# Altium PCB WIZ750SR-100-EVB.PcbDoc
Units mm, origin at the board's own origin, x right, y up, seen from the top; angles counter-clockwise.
Board outline 105 x 70 mm, 2 copper layers (Top Layer, Bottom Layer); 94 components, 77 nets, 337 pads, 84 vias.
Unrouted connection lines stored in the file: 2.
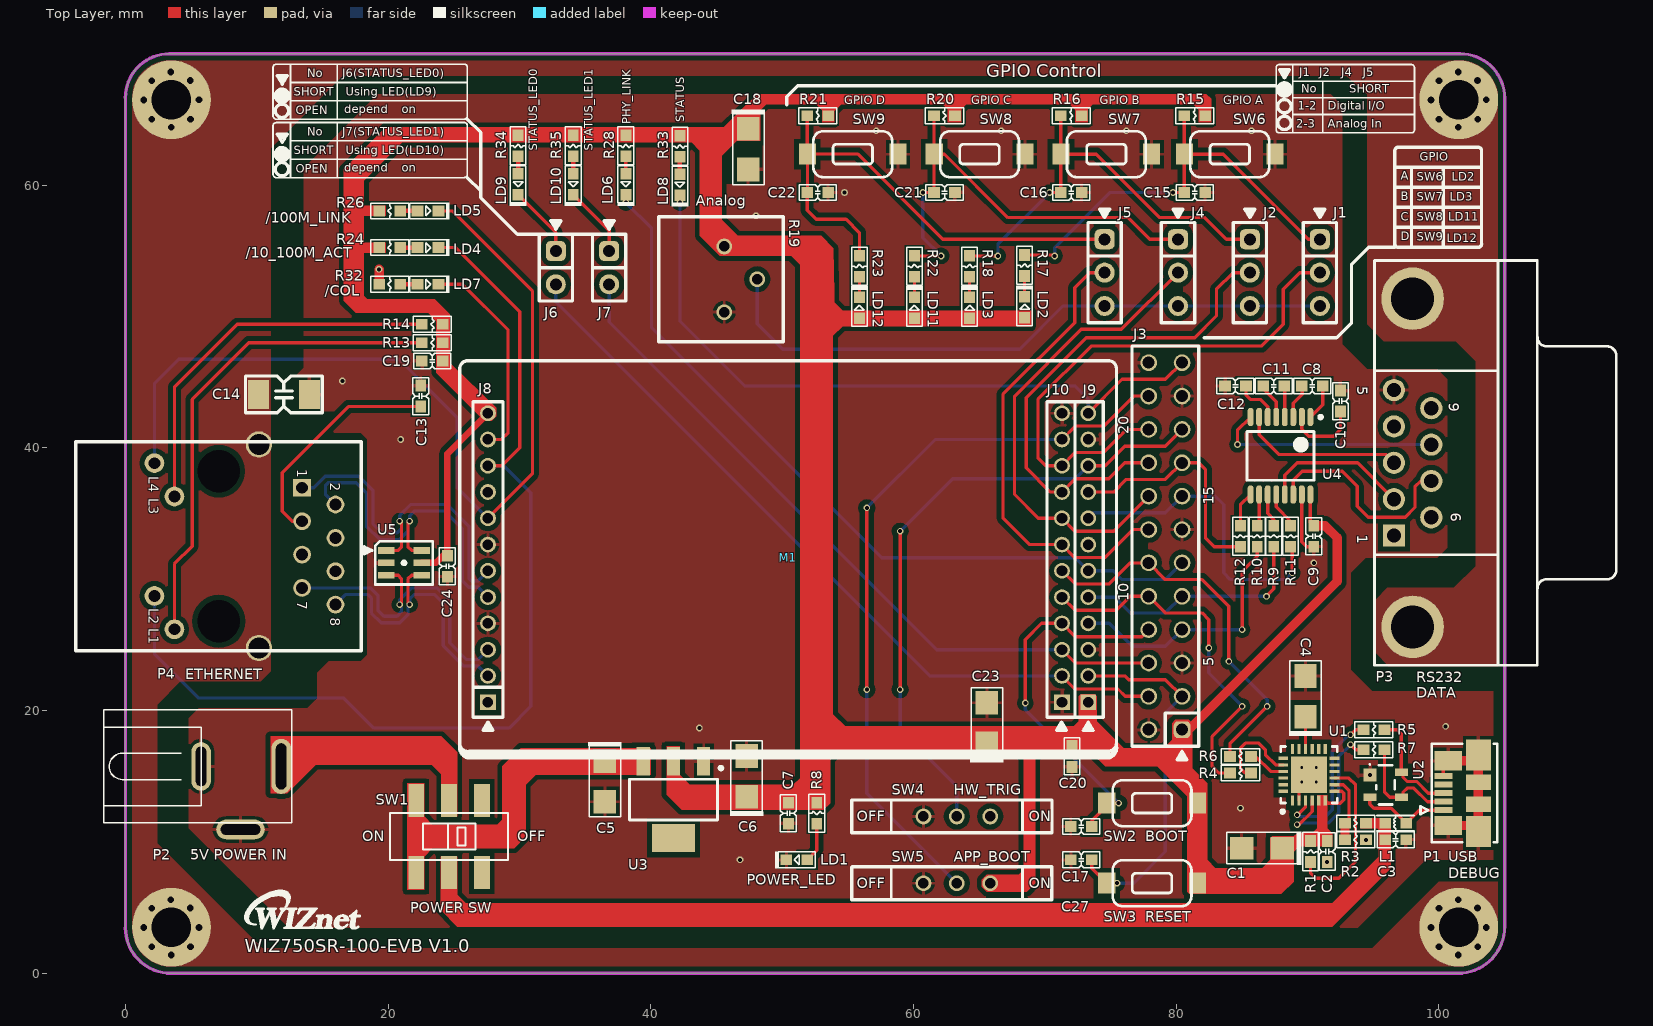
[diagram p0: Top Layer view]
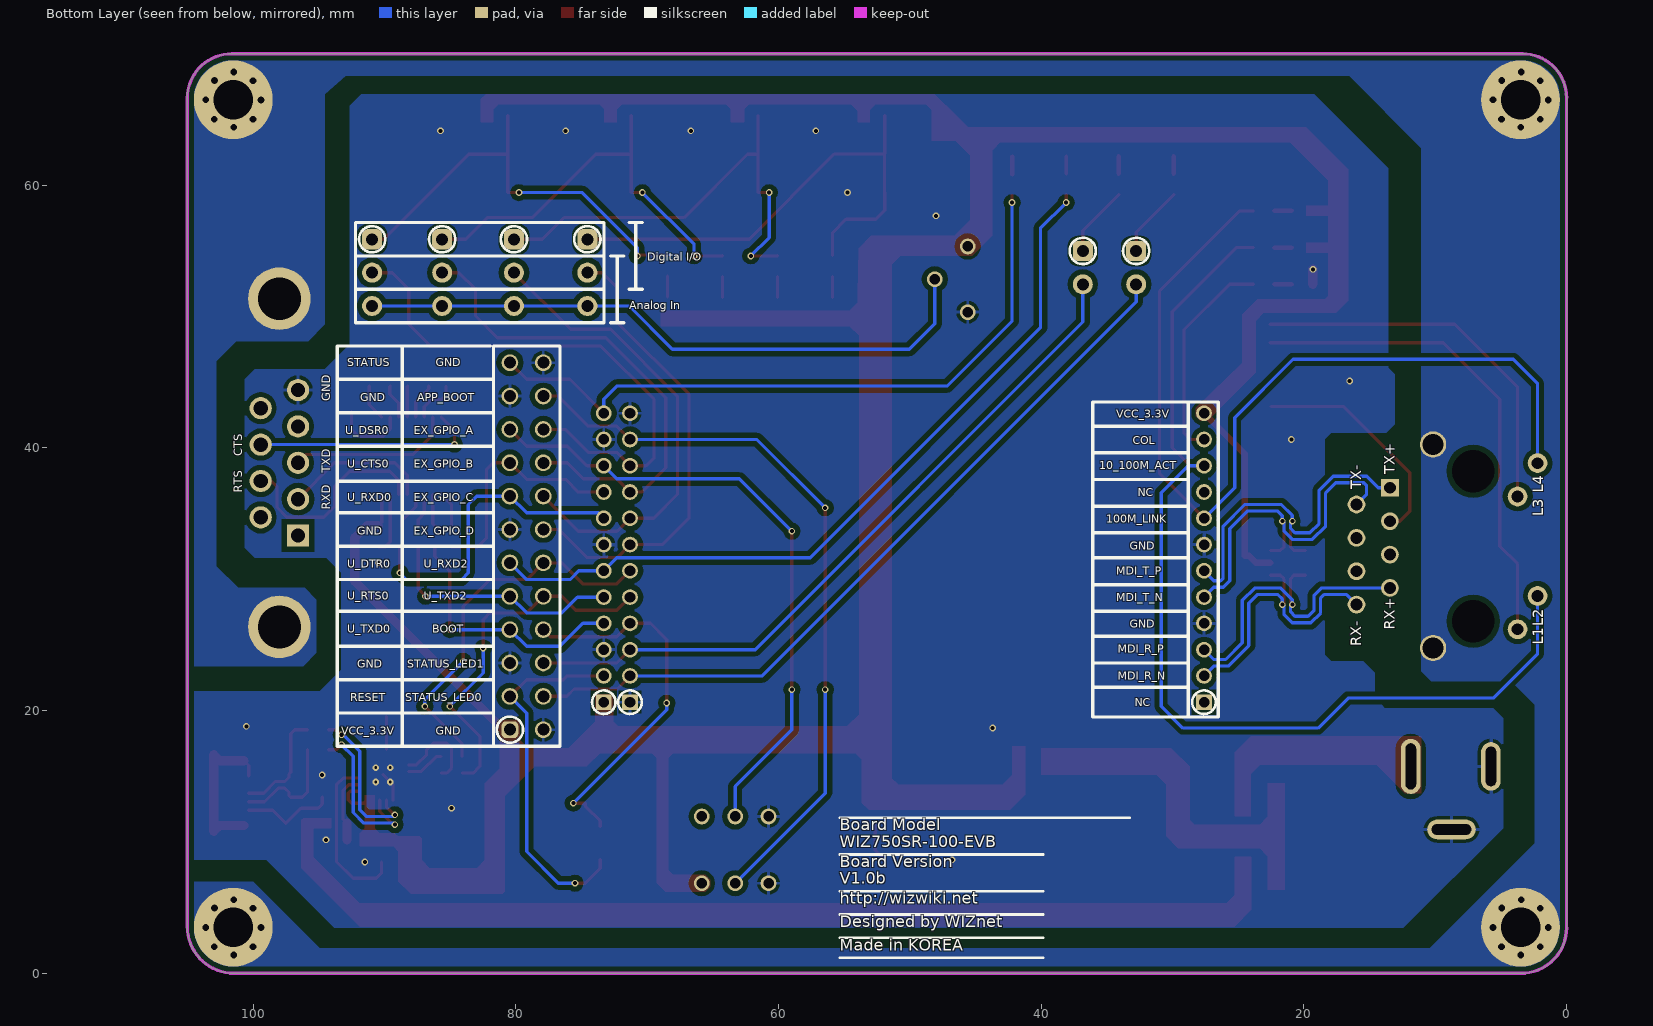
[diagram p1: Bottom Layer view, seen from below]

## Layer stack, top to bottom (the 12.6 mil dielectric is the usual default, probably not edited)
Top Solder: solder mask 0.0102, Solder Resist, Dk 3.5
Top Layer: signal copper 0.0356
Dielectric 1: dielectric 0.32, FR-4, Dk 4.8
Bottom Layer: signal copper 0.0356
Bottom Solder: solder mask 0.0102, Solder Resist, Dk 3.5

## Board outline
0,3.458 ccw(c3.458,3.458) 3.458,0 101.448,0 ccw(c101.448,3.555) 105.004,3.555 105.004,66.625 ccw(c101.629,66.625) 101.629,70 3.347,70 ccw(c3.347,66.653) 0,66.653 0.004,66.653

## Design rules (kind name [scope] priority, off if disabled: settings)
Clearance [All] p1: gap=0.15 except(0.381: Arc-Poly Track-Poly SMDPad-Poly THPad-Poly Via-Poly Fill-Poly Poly-Poly Poly-Region)
DiffPairsRouting [All] p1: maxlimit=0.25 minlimit=0.25 mostfreqgap=0.25 toplayer_minwidth=0.25 toplayer_maxwidth=0.25 toplayer_prefwidth=0.25 bottomlayer_minwidth=0.25 bottomlayer_maxwidth=0.25 bottomlayer_prefwidth=0.25 maxuncoupledlength=12.7
PolygonConnect PolygonConnect_2 [IsPad vs IsNamedPolygon('TOP-GND')Or IsNamedPolygon('BOTTOM-GND')] p1: connectstyle=Relief reliefconductorwidth=0.254 reliefentries=4 polygonreliefangle="90 Angle" airgapwidth=0.254
PolygonConnect PolygonConnect_1 [IsVia] p2: connectstyle=Direct reliefconductorwidth=0.254 reliefentries=4 polygonreliefangle="90 Angle" airgapwidth=0.254
PolygonConnect [All] p3: connectstyle=Direct reliefconductorwidth=0.254 reliefentries=4 polygonreliefangle="90 Angle" airgapwidth=0.254
RoutingVias [All] p1: holewidth=0.305 width=0.508 viastyle="Through Hole" minholewidth=0.305 minwidth=0.508 maxholewidth=0.508 maxwidth=0.762
SolderMaskExpansion [All] p1: expansion=0.102
Width [All] p1: maxlimit=0.705 minlimit=0.25 preferedwidth=0.25 minimp=50.000000 maximp=50.000000 favimp=50.000000
29 further rules are at their usual default settings.

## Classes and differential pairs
differential pair D: +D_P -D_N
differential pair MDI_R: +MDI_R_P -MDI_R_N
differential pair MDI_T: +MDI_T_P -MDI_T_N
differential pair USB_D: +USB_D_P -USB_D_N

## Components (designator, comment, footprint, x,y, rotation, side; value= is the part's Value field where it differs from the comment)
C1 "4.7uF/16V" "CAP-A Size" 86.529,9.525 r180 top
C2 "0.1uF" CAP-0603 91.491,9.271 r90 top
C3 "0.1uF" CAP-0603 96.698,10.16 r180 top
C4 "4.7uF/16V" "CAP-A Size" 89.84,21.082 r90 top
C5 "10uF/16V" "CAP-A Size" 36.5,14.605 r270 top
C6 "10uF/16V" "CAP-A Size" 47.295,14.986 r90 top
C7 "0.1uF" CAP-0603 50.47,12.192 r90 top
C8 "0.1uF" CAP-0603 90.348,44.704 r180 top
C9 "0.1uF" CAP-0603 90.475,33.274 r90 top
C10 "0.1uF" CAP-0603 92.507,43.561 r270 top
C11 "0.1uF" CAP-0603 87.427,44.704 r180 top
C12 "0.1uF" CAP-0603 84.506,44.704 r0 top
C13 "0.1uF" CAP-0603 22.479,43.942 r270 top
C14 "1nF/2kV" CAP-1808 12.065,44.069 r180 top
C15 "0.1uF" CAP-0603 81.407,59.436 r180 top
C16 "0.1uF" CAP-0603 72.009,59.436 r180 top
C17 "0.1uF" CAP-0603 72.771,11.176 r0 top
C18 "4.7uF/16V" "CAP-A Size" 47.422,62.738 r270 top
C19 "0.1uF" CAP-0603 23.368,46.609 r0 top
C20 "0.1uF" CAP-0603 72.06,16.51 r90 top
C21 "0.1uF" CAP-0603 62.357,59.436 r180 top
C22 "0.1uF" CAP-0603 52.705,59.436 r180 top
C23 "4.7uF/16V" "CAP-A Size" 65.583,19.05 r90 top
C24 "0.1uF" CAP-0603 24.511,30.988 r270 top
C27 "0.1uF" CAP-0603 72.771,8.636 r0 top
J1 "2.54mm 1x3 Pin Header DIP" IDC-1X3 90.932,55.88 r270 top
J2 "2.54mm 1x3 Pin Header DIP" IDC-1X3 85.598,55.88 r270 top
J3 "2.54mm 2x12 Pin" IDC-2x12_socket_2.54mm 80.442,18.542 r90 top
J4 "2.54mm 1x3 Pin Header DIP" IDC-1X3 80.137,55.88 r270 top
J5 "2.54mm 1x3 Pin Header DIP" IDC-1X3 74.549,55.88 r270 top
J6 "2.54mm 1x2 Pin Header DIP" IDC-1X2 32.766,54.991 r270 top
J7 "2.54mm 1x2 Pin Header DIP" IDC-1X2 36.83,54.991 r270 top
L1 "HH-1M1608-121JT" IND-0603 96.698,11.43 r180 top
LD1 "RED-0603" LED-0603-RED 51.105,8.636 r180 top
LD2 "GREEN-0603" LED-0603-GREEN 68.453,50.711 r90 top
LD3 "GREEN-0603" LED-0603-GREEN 64.262,50.66 r90 top
LD4 "GREEN-0603" LED-0603-GREEN 23.038,55.245 r0 top
LD5 "YELLOW-0603" LED-0603-YELLOW 23.038,58.039 r0 top
LD6 "BLUE-0603" LED-0603-GREEN 38.1,60.071 r270 top
LD7 "GREEN-0603" LED-0603-GREEN 23.038,52.451 r0 top
LD8 "GREEN-0603" LED-0603-GREEN 42.215,60.033 r270 top
LD9 "GREEN-0603" LED-0603-GREEN 29.896,60.071 r270 top
LD10 "GREEN-0603" LED-0603-GREEN 34.087,60.071 r270 top
LD11 "GREEN-0603" LED-0603-GREEN 60.071,50.66 r90 top
LD12 "GREEN-0603" LED-0603-GREEN 55.88,50.66 r90 top
M1 "WIZ750SR-100_V1.0" WIZ750JR_V1.0 25.451,16.637 r0 top
P1 "47346-0001" USB-MICRO-B(SMD) 104.445,13.716 r180 top
P2 "DC-JACK 2pi" "DC-JACK 2pi" 8.763,15.748 r270 top
P3 "D-SUB9-MALE" D-SUB9-MALE 107.493,38.862 r270 top
P4 "BS-RB10005" RJ45-125BAG1A 7.112,32.512 r270 top
R1 "4.7K" RES-0603 90.221,9.271 r90 top
R2 "47K" RES-0603 93.65,10.16 r180 top
R3 "24K" RES-0603 93.65,11.43 r0 top
R4 "0R" RES-0603 84.887,15.24 r180 top
R5 "22R" RES-0603 95.047,17.018 r180 top
R6 "0R" RES-0603 84.887,16.51 r180 top
R7 "22R" RES-0603 95.047,18.542 r180 top
R8 "330R" RES-0603 52.629,12.192 r270 top
R9 "0R" RES-0603 87.427,33.274 r90 top
R10 "0R" RES-0603 86.157,33.274 r90 top
R11 "0R" RES-0603 88.697,33.274 r90 top
R12 "0R" RES-0603 84.887,33.274 r90 top
R13 "330R" RES-0603 23.368,48.006 r180 top
R14 "330R" RES-0603 23.368,49.403 r180 top
R15 "4.7K" RES-0603 81.407,65.278 r0 top
R16 "4.7K" RES-0603 72.009,65.278 r0 top
R17 "330R" RES-0603 68.453,53.886 r90 top
R18 "330R" RES-0603 64.262,53.835 r90 top
R19 "WIW3386P" WIW3386P 45.593,52.832 r90 top
R20 "4.7K" RES-0603 62.357,65.278 r0 top
R21 "4.7K" RES-0603 52.705,65.278 r0 top
R22 "330R" RES-0603 60.071,53.835 r90 top
R23 "330R" RES-0603 55.88,53.835 r90 top
R24 "330R" RES-0603 20.117,55.245 r180 top
R26 "330R" RES-0603 20.117,58.039 r180 top
R28 "1K" RES-0603 38.1,62.992 r90 top
R32 "330R" RES-0603 20.117,52.451 r180 top
R33 "330R" RES-0603 42.215,62.954 r90 top
R34 "330R" RES-0603 29.896,62.992 r90 top
R35 "330R" RES-0603 34.087,62.992 r90 top
SW1 "Switch" JS202011SCQN 24.638,10.414 r0 top
SW2 "ITS-1107(SMD)" ITS-1107(SMD) 78.156,12.954 r0 top
SW3 "ITS-1107(SMD)" ITS-1107(SMD) 78.156,6.858 r0 top
SW4 "ITS-12H" ITS-12H 63.297,11.938 r180 top
SW5 "ITS-12H" ITS-12H 63.297,6.858 r180 top
SW6 "ITS-1107(SMD)" ITS-1107(SMD) 84.074,62.357 r180 top
SW7 "ITS-1107(SMD)" ITS-1107(SMD) 74.676,62.357 r180 top
SW8 "ITS-1107(SMD)" ITS-1107(SMD) 65.024,62.357 r180 top
SW9 "ITS-1107(SMD)" ITS-1107(SMD) 55.372,62.357 r180 top
U1 "CP2104-GM" CP2104_QFN24_PAD 90.094,15.113 r90 top
U2 "SP0503BAHTG" SP0503BAHTG 95.936,14.351 r0 top
U3 "IL1117C-33ET" IL1117C-33ET 41.723,13.218 r270 top
U4 "SP3232EBEY" SP3232EBEY-TSSOP16 87.935,39.395 r270 top
U5 "TPD4S009" SOT-23-6L 21.209,31.242 r0 top

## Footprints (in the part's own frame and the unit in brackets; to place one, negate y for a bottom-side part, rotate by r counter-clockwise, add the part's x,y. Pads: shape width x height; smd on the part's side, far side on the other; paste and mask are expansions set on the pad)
CAP-0603 [mm] "Ceramic CAP 0603(1608)"
  rect 0.89x0.82 smd: 1(-0.8,0) 2(0.8,0)
  silkscreen extent -1.41,-0.6 1.41,0.6, body extent -0.93,-0.41 0.93,0.41, height 0.81
CAP-1808 [mm] "Ceramic CAP 1808(4520)"
  rect 1.6x2.2 smd: 1(-1.95,0) 2(1.95,0)
  silkscreen extent -2.92,-1.4 2.92,1.4, body extent -2.25,-1.02 2.25,1.01, height 2
"CAP-A Size" [mm] "Tantal CAP A Size EIA/IECQ 3216"
  rect 1.8x1.7 smd: 1(-1.55,0) 2(1.55,0)
  silkscreen extent -3,-1.25 2.7,1.25, body extent -1.67,-0.78 1.72,0.82, height 1.75
CP2104_QFN24_PAD [mm] "QFN, 24-Leads, Body 4.00x4.00mm, Pitch 0.50mm, Thermal Pad 2.75x2.75mm, IPC Medium Density"
  rect 0.75x0.25 smd: 1(-1.95,1.25) 2(-1.95,0.75) 3(-1.95,0.25) 4(-1.95,-0.25) 5(-1.95,-0.75) 6(-1.95,-1.25) 13(1.95,-1.25) 14(1.95,-0.75) 15(1.95,-0.25) 16(1.95,0.25) 17(1.95,0.75) 18(1.95,1.25)
  rect 0.25x0.75 smd: 7(-1.25,-1.95) 8(-0.75,-1.95) 9(-0.25,-1.95) 10(0.25,-1.95) 11(0.75,-1.95) 12(1.25,-1.95) 19(1.25,1.95) 20(0.75,1.95) 21(0.25,1.95) 22(-0.25,1.95) 23(-0.75,1.95) 24(-1.25,1.95)
  rect 2.75x2.75 smd: 25(0,0)
  silkscreen extent -2.92,-2.15 2.15,2.15, body extent -2,-2 2,2, height 0.8
D-SUB9-MALE [mm] "D-SUB9, MALE, Right Angle;"
  rect 1.69x1.69 hole 1.09: 1(5.54,-10.92)
  round 1.69 hole 1.09: 2(2.77,-10.92) 3(0,-10.92) 4(-2.77,-10.92) 5(-5.54,-10.92) 6(4.155,-8.08) 7(1.385,-8.08) 8(-1.385,-8.08) 9(-4.155,-8.08)
  round 4.76 hole 3.26: 10(-12.495,-9.5) 11(12.495,-9.5)
  silkscreen extent -15.4,-12.4 15.4,6, body extent -15.38,-12.55 15.43,6.05, height 12.57
"DC-JACK 2pi" [mm] "DC-JACK 2pi"
  oval 4.2x1.5 hole 0.8 slot 3.5 at 0 deg: 1(0,3.1)
  oval 1.5x3.7 hole 0.8 slot 3 at 90 deg: 2(4.8,0)
  oval 3.7x1.5 hole 0.8 slot 3 at 0 deg: 3(0,-3)
  silkscreen extent -4.3,-10.4 4.3,3.9, body extent -4.42,-10.49 5.05,3.99, height 11.18
IDC-1X2 [mil]
  rrect50% 60x60 hole 36: 1(0,0)
  round 60 hole 36: 2(100,0)
  silkscreen extent -90,-50 150,50, body extent -49,-49 151,51, height 336
IDC-1X3 [mil]
  rrect50% 60x60 hole 36: 1(0,0)
  round 60 hole 36: 2(100,0) 3(200,0)
  silkscreen extent -90,-50 250,50, body extent -46,-49 254,49, height 323
IDC-2x12_socket_2.54mm [mil] "IDC-2x12_HEADER"
  rrect50% 50x50 hole 36: 1(0,0)
  round 50 hole 36: 2(0,100) 3(100,0) 4(100,100) 5(200,0) 6(200,100) 7(300,0) 8(300,100) 9(400,0) 10(400,100) 11(500,0) 12(500,100) 13(600,0) 14(600,100) 15(700,0) 16(700,100) 17(800,0) 18(800,100) 19(900,0) 20(900,100) 21(1000,0) 22(1000,100) 23(1100,0) 24(1100,100)
  silkscreen extent -90,-50 1150,150, body extent -60,-45 1160,155, height 325
IL1117C-33ET [mm] "SOT223, 4-Leads, Body 6.45x7.80mm (avg), Pitch 2.30mm, IPC Medium Density"
  rect 2.15x1 smd: 1(-2.925,2.3) 2(-2.925,0) 3(-2.925,-2.3)
  rect 2.15x3.25 smd: 4(2.925,0)
  silkscreen extent -2.53,-3.35 1.55,3.74, body extent -3.54,-3.25 3.54,3.25, height 1.65
IND-0603 [mm]
  rect 0.89x0.82 smd: 1(-0.8,0) 2(0.8,0)
  silkscreen extent -1.4,-0.6 1.4,0.6, body extent -0.8,-0.4 0.8,0.4, height 0.95
ITS-12H [mm] "Silde Switch"
  round 1.2 hole 0.8: 1(0,0) 2(-2.54,0) 3(2.54,0)
  silkscreen extent -5,-1.25 5,1.25, body extent -5,-1.22 5,1.22, height 6.4
ITS-1107(SMD) [mm] "TACT SW, SMD"
  rect 1.3x1.6 smd: 1(-3.45,0) 2(3.45,0)
  silkscreen extent -3,-1.75 3,1.75, body extent -3.05,-1.85 3.05,1.85, height 2.5
JS202011SCQN [mm]
  rect 1.2x2.5 smd: 1(-2.5,-2.75) 2(0,-2.75) 3(2.5,-2.75) 4(-2.5,2.75) 5(0,2.75) 6(2.5,2.75)
  silkscreen extent -4.5,-1.8 4.5,1.8, body extent -4.52,-3.75 4.52,3.75, height 5.5
LED-0603-GREEN [mm]
  rect 0.89x0.82 smd: 1(-0.8,0) 2(0.8,0)
  silkscreen extent -1.41,-0.65 1.65,0.65, body extent -0.85,-0.45 0.85,0.45, height 0.9
LED-0603-RED [mm]
  rect 0.89x0.82 smd: 1(-0.8,0) 2(0.8,0)
  silkscreen extent -1.41,-0.65 1.65,0.65, body extent -0.85,-0.45 0.85,0.45, height 0.9
LED-0603-YELLOW [mm]
  rect 0.89x0.82 smd: 1(-0.8,0) 2(0.8,0)
  silkscreen extent -1.41,-0.65 1.65,0.65, body extent -0.8,-0.4 0.8,0.4, height 0.6
RES-0603 [mm] "RES-0603"
  rect 0.89x0.82 smd: 1(-0.8,0) 2(0.8,0)
  silkscreen extent -1.45,-0.6 1.45,0.6, body extent -0.82,-0.41 0.82,0.41, height 0.46
RJ45-125BAG1A [mm]
  round 1.5 hole 0.89: L1(6.325,-3.38) L2(3.785,-4.9) L3(-3.785,-3.38) L4(-6.325,-4.9)
  rect 1.35x1.35 hole 0.9: R1(-4.445,6.34)
  round 1.35 hole 0.9: R2(-3.175,8.88) R3(-1.905,6.34) R4(-0.635,8.88) R5(0.635,6.34) R6(1.905,8.88) R7(3.175,6.34) R8(4.445,8.88)
  round 2 hole 1.6: R9(-7.75,3.05) R10(7.75,3.05)
  round 1.8 hole 3.25: ""(-5.715,0) ""(5.715,0)
  silkscreen extent -7.95,-10.89 7.95,10.83, body extent -8.03,-10.8 7.97,10.5, height 13.1
SOT-23-6L [mm]
  rect 1.27x0.508 smd: 1(-1.34,0.95) 2(-1.34,0) 3(-1.34,-0.95) 4(1.34,-0.95) 5(1.34,0) 6(1.34,0.95)
  silkscreen extent -3.02,-1.65 2.2,1.65, body extent -1.21,-1.4 1.21,1.4, height 1.09
SP0503BAHTG [mm] "SOT143, 4-Leads, Body 2.92x2.37mm, Pitch 1.90mm, IPC Medium Density"
  rect 1x1 smd: 1(-1.2,0.75)
  rect 1x0.6 smd: 2(-1.2,-0.95) 3(1.2,-0.95) 4(1.2,0.95)
  silkscreen extent -1.25,-1.5 0.7,1.6, body extent -0.7,-1.52 0.7,1.52, height 1.22
SP3232EBEY-TSSOP16 [mm] "True +3.0V to +5.5V RS-232 Transceivers"
  oval 1.4x0.45 smd: 1(-2.95,2.275) 2(-2.95,1.625) 3(-2.95,0.975) 4(-2.95,0.325) 5(-2.95,-0.325) 6(-2.95,-0.975) 7(-2.95,-1.625) 8(-2.95,-2.275) 9(2.95,-2.275) 10(2.95,-1.625) 11(2.95,-0.975) 12(2.95,-0.325) 13(2.95,0.325) 14(2.95,0.975) 15(2.95,1.625) 16(2.95,2.275)
  silkscreen extent -3.07,-2.55 1.85,3.17, body extent -3.16,-2.49 3.12,2.51, height 1.09
USB-MICRO-B(SMD) [mm] "MOLEX SD-47346-001"
  rect 1.38x0.45 smd: 1(4.11,1.3) 2(4.11,0.65) 3(4.11,0) 4(4.11,-0.65) 5(4.11,-1.3)
  rect 2.1x1.475 smd: 6(3.75,2.462) 7(3.75,-2.462)
  rect 1.9x2.375 smd: 8(1.45,2.913) 11(1.45,-2.913)
  rect 1.9x1.175 smd: 9(1.45,0.837) 10(1.45,-0.837)
  silkscreen extent 0,-3.75 5.85,3.75, body extent -0.43,-4.1 5,4.1, height 2.98
WIW3386P [mm] "Potentiometer 10KR, Hongxing, 8mm shaft"
  round 1.2 hole 0.8: 1(2.5,0) 2(0,-2.5) 3(-2.5,0)
  silkscreen extent -4.75,-4.5 4.75,5, body extent -3.3,-3.3 3.3,3.75, height 4.7
WIZ750JR_V1.0 [mm] "WIZ750JR_V1.0, Serial to Ethernet Module, W7500P"
  rect 1.2x1.2 hole 0.8: J1-1(47.85,4) J2-1(2.15,4) J3-1(45.85,4)
  round 1.2 hole 0.8: J1-2(47.85,6) J1-3(47.85,8) J1-4(47.85,10) J1-5(47.85,12) J1-6(47.85,14) J1-7(47.85,16) J1-8(47.85,18) J1-9(47.85,20) J1-10(47.85,22) J1-11(47.85,24) J1-12(47.85,26) J2-2(2.15,6) J2-3(2.15,8) J2-4(2.15,10) J2-5(2.15,12) J2-6(2.15,14) J2-7(2.15,16) J2-8(2.15,18) J2-9(2.15,20) J2-10(2.15,22) J2-11(2.15,24) J2-12(2.15,26) J3-2(45.85,6) J3-3(45.85,8) J3-4(45.85,10) J3-5(45.85,12) J3-6(45.85,14) J3-7(45.85,16) J3-8(45.85,18) J3-9(45.85,20) J3-10(45.85,22) J3-11(45.85,24) J3-12(45.85,26)
  silkscreen extent 0,0 50,30, body extent 1.13,2.79 48.75,26.79, height 6

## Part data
C1 C4 C5 C6 C18 C23: library part "CAP-A Size", "Tantla CAP A Size EIA/IECQ 3216"
C2 C3 C7 C8 C9 C10 C11 C12 C13 C15 C16 C17 C19 C20 C21 C22 C24 C27: library part CAP-0603, "Ceramic CAP 0603(1608)"
C14: library part CAP-1808, "Ceramic CAP 1808(4520)"
J3: library part "Header 2x12", "pin header 2.54mm 2x12"
J6 J7: library part "Header 1x2", "pin header 2.54mm 1x2"
L1: library part IND-0603, "Inductor 0603(1608)"
LD1 LD2 LD3 LD4 LD5 LD6 LD7 LD8 LD9 LD10 LD11 LD12: library part LED-0603, "LED-0603"
M1: library part WIZ750JR_V0.2, "Serial to ethernet module, 50mmx30mm, 7500 + External PHY"
P1: "MICRO USB B Type"
P3: "D-SUB-9, MALE,  Right Angle"
P4: library part RB1-125BAG1A, "10/100 BASE-TX MAGJACK"
R1 R2 R3 R4 R5 R6 R7 R8 R9 R10 R11 R12 R13 R14 R15 R16 R17 R18 R20 R21 R22 R23 R24 R26 R28 R32 R33 R34 R35: library part RES-0603, "RES-0603"
R19: "Potentiometer"
SW1: "SMD slide Switch (ON-ON)"
SW2 SW3 SW6 SW7 SW8 SW9: "TACT SW, SMD"
SW4 SW5: "Slide Switch"
U1: "USB to UART Bridge, SiliconLabs"
U2: "Little Fuse, Silicon Protection Array Products"
U3: "1A, 3.3V"
U4: "True +3.0V to +5.5V RS-232 Transceivers TSSOP16"
U5: library part tpd4s009, "6-PIN SOT DBVor DCK Package"

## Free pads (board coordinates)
  round 6 hole 3: ""(3.5,3.5) ""(3.5,66.5) ""(101.5,3.5) ""(101.5,66.5)

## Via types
v1: diameter 0.508, hole 0.305, Top Layer to Bottom Layer, tented both sides, 48 vias
v2: diameter 0.762, hole 0.508, Top Layer to Bottom Layer, tented both sides, 32 vias
v3: diameter 0.5, hole 0.2, Top Layer to Bottom Layer, 4 vias

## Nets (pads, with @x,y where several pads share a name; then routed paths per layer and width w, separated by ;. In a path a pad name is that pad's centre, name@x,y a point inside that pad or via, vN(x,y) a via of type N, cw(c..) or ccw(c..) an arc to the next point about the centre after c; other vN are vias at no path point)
5V: C5.1 SW1.1 SW1.4 U3.3
100M_LINK_LED: LD5.2 M1.J2-8 P4.L4 | length 68.7
  Top Layer w0.25: LD5.2 24.892,58.039 30.988,51.943 30.988,38.024 M1.J2-8
  Bottom Layer w0.25: P4.L4 2.212,44.884 4.064,46.736 20.828,46.736 25.273,42.291 25.273,36.965 M1.J2-8
ACT_LED: LD4.2 M1.J2-10 P4.L2 | length 78
  Top Layer w0.25: LD4.2 25.146,55.245 30.023,50.368 30.023,40.005 28.655,38.637 M1.J2-10
  Bottom Layer w0.25: P4.L2 2.212,24.331 5.588,20.955 16.637,20.955 18.923,18.669 29.21,18.669 30.861,20.32 30.861,36.576 28.8,38.637 M1.J2-10
ADC0: J1.3 J2.3 J4.3 J5.3 R19.2 | length 48.4
  Bottom Layer w0.25: R19.2 48.093,49.443 50.038,47.498 68.072,47.498 71.374,50.8 J5.3 J4.3 J2.3 J1.3
APP_BOOT: J3.22 M1.J3-11 SW5.1 | length 56.4
  Top Layer w0.25: v1(56.439,21.59) v1(56.439,35.433) ; M1.J3-11 72.32,41.656 74.473,41.656 76.759,43.942 J3.22
  Bottom Layer w0.25: v1(56.439,21.59) 56.439,13.716 SW5.1 ; v1(56.439,35.433) 61.643,40.637 M1.J3-11
BOOT: C17.2 J3.8 M1.J3-4 SW2.1 | length 29.1
  Top Layer w0.25: v1(68.504,20.574) 68.504,25.4 69.741,26.637 M1.J3-4 72.309,25.629 77.368,25.629 J3.8 ; C17.2 73.571,11.595 74.706,12.73 SW2.1 v1(75.616,12.954)
  Bottom Layer w0.25: v1(68.504,20.574) 68.504,20.066 v1(75.616,12.954)
CH_GND: C14.2 P3.10 P3.11 P4.R9 P4.R10 pad.
  other v2: 3.478,1.398 101.478,1.398 2.005,2.008 4.951,2.008 100.005,2.008 102.951,2.008 1.395,3.481 5.598,3.49 99.395,3.481 103.598,3.49 2.005,4.954 4.938,4.963 100.005,4.954 102.938,4.963 3.46,5.609 101.46,5.609 3.478,64.398 101.478,64.398 2.005,65.008 4.951,65.008 100.005,65.008 102.951,65.008 1.395,66.481 99.395,66.481 5.598,66.49 103.598,66.49 2.005,67.954 100.005,67.954 4.938,67.963 102.938,67.963 3.46,68.609 101.46,68.609
COL_LED: LD7.2 M1.J2-11 | length 16.3
  Top Layer w0.25: LD7.2 25.654,52.451 29.134,48.971 29.134,41.148 28.623,40.637 M1.J2-11
D_N: P1.2 R5.1 U2.3 | length 8.7
  Top Layer w0.25: R5.1 95.847,13.805 96.251,13.401 U2.3 97.261,13.526 97.261,13.775 97.587,14.101 98.091,14.101 99.126,13.066 P1.2
D_P: P1.3 R7.1 U2.4 | length 8.3
  Top Layer w0.25: R7.1 96.825,18.542 97.136,18.231 U2.4 97.261,15.176 97.261,14.927 97.587,14.601 98.298,14.601 99.183,13.716 P1.3
DB_CTS: P3.8 U4.8 | length 17.3
  Top Layer w0.25: v1(84.657,40.259) 84.657,41.342 U4.8
  Bottom Layer w0.25: v1(84.657,40.259) 84.645,40.247 P3.8
DB_RTS: P3.7 U4.14 | length 16.3
  Top Layer w0.25: U4.14 88.91,37.551 89.586,38.227 92.634,38.227 93.777,37.084 93.777,35.56 94.615,34.722 97.434,34.722 98.171,35.458 98.171,37.033 98.615,37.477 P3.7
DB_RXD: P3.2 U4.13 | length 11.3
  Top Layer w0.25: U4.13 88.26,37.917 89.205,38.862 93.803,38.862 P3.2
DB_TXD: P3.3 U4.7 | length 12.5
  Top Layer w0.25: U4.7 86.31,40.995 87.808,39.497 95.938,39.497 P3.3
EX_GPIO_A: J1.2 J3.20 M1.J3-10 | length 41.3
  Top Layer w0.25: J3.20 76.225,41.402 74.473,39.649 72.313,39.649 M1.J3-10 70.075,38.637 69.469,39.243 69.469,43.688 73.533,47.752 86.487,47.752 88.138,49.403 88.138,52.07 89.408,53.34 J1.2
EX_GPIO_B: J2.2 J3.18 M1.J3-9 | length 38.5
  Top Layer w0.25: J3.18 76.073,38.862 74.854,37.643 72.307,37.643 M1.J3-9 70.424,36.637 68.58,38.481 68.58,43.815 73.152,48.387 81.407,48.387 83.058,50.038 83.058,52.07 84.328,53.34 J2.2
EX_GPIO_C: J3.16 J4.2 M1.J3-8 | length 36.3
  Top Layer w0.25: J3.16 75.235,33.655 72.283,33.655 M1.J3-8 69.503,34.637 67.691,36.449 67.691,43.942 72.771,49.022 75.819,49.022 J4.2
EX_GPIO_D: J3.14 J5.2 M1.J3-7 | length 35.8
  Top Layer w0.25: J5.2 73.406,53.34 72.263,52.197 72.263,49.53 66.802,44.069 66.802,34.671 68.836,32.637 M1.J3-7 72.289,31.648 74.556,31.648 76.69,33.782 J3.14
GND: C1.2 C2.1 C3.1 C4.2 C5.2 C6.2 C7.1 C9.1 C10.1 C12.1 C13.1 C14.1 C15.1 C16.1 C17.1 C18.2 C19.1 C20.1 C21.1 C22.1 C23.2 C24.2 C27.1 J3.2 J3.5 J3.13 J3.21 J3.24 LD1.2 M1.J1-3 M1.J1-7 M1.J1-11 M1.J2-4 M1.J2-7 M1.J3-1 M1.J3-12 P1.5 P1.6 P1.7 P1.8 P1.9 P1.10 P1.11 P2.2 P2.3 P3.5 R2.1 R19.3 R32.2 SW4.3 SW5.3 SW6.1 SW7.1 SW8.1 SW9.1 U1.2 U1.25 U2.1 U3.1 U4.15 U5.2 | length 20.2
  Top Layer w0.25: U1.2 89.344,14.363 v3(89.544,14.563) U1.25 ; U4.15 89.56,32.852 89.938,32.474 C9.1 ; P1.5 100.335,15.819 P1.7
  Top Layer w0.705: v1(19.304,53.594) 19.317,53.581 R32.2 ; P1.6 102.545,11.254 P1.8 P1.9 P1.10 P1.11 102.545,16.178 P1.7
  other v1: 91.491,8.471 46.787,8.636 94.45,10.16 84.887,12.573 94.736,15.101 43.688,18.669 100.508,18.796 90.475,31.242 20.955,40.64 16.51,45.085 48.006,57.658 54.737,59.436 57.15,64.135 66.675,64.135 76.2,64.135 85.725,64.135
  other v3: 90.644,14.563 89.544,15.663 90.644,15.663
LED_SW0: C15.2 J1.1 R15.1 R17.2 SW6.2 | length 33.4
  Top Layer w0.25: R17.2 70.663,54.686 v1(70.739,54.61) ; v1(79.756,59.436) C15.2 R15.1 ; SW6.2 83.566,62.357 90.043,55.88 J1.1
  Bottom Layer w0.25: v1(70.739,54.61) 70.739,55.245 74.93,59.436 v1(79.756,59.436)
LED_SW1: C16.2 J2.1 R16.1 R18.2 SW7.2 | length 32.4
  Top Layer w0.25: R18.2 64.287,54.61 v1(66.421,54.61) ; v1(70.358,59.436) C16.2 SW7.2@71.209,62.374 ; R16.1 SW7.2@71.209,62.374 ; J2.1 83.82,55.88 82.169,57.531 78.74,57.531 73.914,62.357 SW7.2 SW7.2@71.209,62.374
  Bottom Layer w0.25: v1(66.421,54.61) 66.421,55.499 v1(70.358,59.436)
LED_SW2: C21.2 J4.1 R20.1 R22.2 SW8.2 | length 35.4
  Top Layer w0.25: R22.2 60.096,54.61 v1(62.103,54.61) ; v1(60.706,59.436) C21.2 SW8.2@61.557,62.34 ; R20.1 SW8.2@61.557,62.34 ; J4.1 77.978,55.88 76.327,57.531 67.183,57.531 62.357,62.357 SW8.2 SW8.2@61.557,62.34
  Bottom Layer w0.25: v1(60.706,59.436) 60.706,56.007 v1(62.103,54.61)
LED_SW3: C22.2 J5.1 R21.1 R23.2 SW9.2 | length 39.2
  Top Layer w0.25: C22.2@51.905,59.182 51.922,59.199 SW9.2 SW9.2@51.905,62.374 ; C22.2 51.905,58.077 52.578,57.404 54.864,57.404 55.88,56.388 R23.2 ; R21.1 SW9.2@51.905,62.374 ; J5.1 62.23,55.88 55.736,62.374 SW9.2@51.905,62.374
MDI_R_N: M1.J2-2 P4.R8 U5.4 | length 22.6
  Top Layer w0.25: v1(21.641,28.067) 21.512,28.196 21.512,30.021 21.783,30.292 U5.4
  Bottom Layer w0.25: P4.R8 16.754,28.829 18.474,28.829 18.728,28.575 18.728,27.424 19.474,26.678 20.887,26.678 21.512,27.303 21.512,27.938 v1(21.641,28.067) 21.641,28.499 21.971,28.829 23.546,28.829 24.189,28.186 24.189,24.95 25.752,23.387 26.851,23.387 M1.J2-2
MDI_R_P: M1.J2-3 P4.R7 U5.3 | length 25.1
  Top Layer w0.25: U5.3 20.762,30.292 21.012,30.042 21.012,28.196 v1(20.883,28.067)
  Bottom Layer w0.25: P4.R7@13.249,29.337 P4.R7@13.257,29.329 ; P4.R7 13.46,29.329 18.681,29.329 19.228,28.782 19.228,27.631 19.681,27.178 20.68,27.178 21.012,27.51 21.012,27.938 v1(20.883,28.067) 20.883,28.448 21.764,29.329 23.753,29.329 24.689,28.393 24.689,25.157 25.959,23.887 26.851,23.887 M1.J2-3
MDI_T_N: M1.J2-5 P4.R2 U5.6 | length 27.2
  Top Layer w0.25: v1(21.641,34.417) 21.512,34.288 21.512,32.463 21.783,32.192 U5.6
  Bottom Layer w0.25: P4.R2 15.24,36.439 15.24,37.16 15.426,37.346 17.569,37.346 18.347,36.568 18.347,34.028 19.347,33.028 20.887,33.028 21.512,33.653 21.512,34.288 v1(21.641,34.417) 21.641,34.849 21.979,35.187 24.304,35.187 25.654,33.837 25.654,29.866 26.133,29.387 26.851,29.387 M1.J2-5
MDI_T_P: M1.J2-6 P4.R1 U5.1 | length 27.8
  Top Layer w0.25: U5.1 20.762,32.192 21.012,32.442 21.012,34.288 v1(20.883,34.417)
  Bottom Layer w0.25: P4.R1 14.33,36.957 15.219,37.846 17.776,37.846 18.847,36.775 18.847,34.235 19.554,33.528 20.68,33.528 21.012,33.86 21.012,34.288 v1(20.883,34.417) 20.883,34.853 21.717,35.687 24.511,35.687 26.154,34.044 26.154,30.073 26.34,29.887 26.851,29.887 M1.J2-6
NetC4_1: C4.1 U1.16 | length 2.5
  Top Layer w0.25: C4.1 89.844,19.528 U1.16
NetC8_1: C8.1 U4.1 | length 2.7
  Top Layer w0.25: U4.1 91.148,43.283 C8.1
NetC8_2: C8.2 U4.3 | length 2.7
  Top Layer w0.25: U4.3 88.91,43.393 89.586,44.069 89.586,44.666 C8.2
NetC10_2: C10.2 U4.2 | length 5.7
  Top Layer w0.25: U4.2 89.56,41.428 90.094,40.894 91.999,40.894 92.507,41.402 C10.2
NetC11_1: C11.1 U4.4 | length 2.4
  Top Layer w0.25: C11.1 88.26,44.671 U4.4
NetC11_2: C11.2 U4.5 | length 2.8
  Top Layer w0.25: C11.2 86.627,44.488 87.61,43.505 U4.5
NetC12_2: C12.2 U4.6 | length 3.5
  Top Layer w0.25: C12.2 85.306,44.031 85.649,43.688 86.411,43.688 86.96,43.139 U4.6
NetC13_2: C13.2 P4.R3 | length 17.4
  Top Layer w0.25: P4.R3 12.7,34.417 11.938,35.179 11.938,38.1 16.98,43.142 C13.2
NetJ6_1: J6.1 LD9.2 | length 5.5
  Top Layer w0.25: LD9.2 32.766,56.401 J6.1
NetJ7_1: J7.1 LD10.2 | length 5.4
  Top Layer w0.25: LD10.2 36.83,56.528 J7.1
NetL1_1: L1.1 P1.1 U2.2 | length 7.1
  Top Layer w0.25: U2.2 94.736,12.884 95.047,12.573 96.355,12.573 L1.1 98.484,12.416 P1.1
NetLD1_1: LD1.1 R8.2 | length 3.1
  Top Layer w0.25: LD1.1 52.629,9.36 R8.2
NetLD2_2: LD2.2 R17.1 | length 1.6
  Top Layer w0.25: LD2.2 R17.1
NetLD3_2: LD3.2 R18.1 | length 1.6
  Top Layer w0.25: LD3.2 R18.1
NetLD4_1: LD4.1 R24.1 | length 1.3
  Top Layer w0.35: R24.1 LD4.1
NetLD5_1: LD5.1 R26.1 | length 1.3
  Top Layer w0.35: R26.1 LD5.1
NetLD6_1: LD6.1 R28.1 | length 1.3
  Top Layer w0.25: LD6.1 R28.1
NetLD7_1: LD7.1 R32.1 | length 1.3
  Top Layer w0.35: R32.1 LD7.1
NetLD8_1: LD8.1 R33.1 | length 1.3
  Top Layer w0.35: LD8.1 R33.1
NetLD9_1: LD9.1 R34.1 | length 1.3
  Top Layer w0.35: LD9.1 R34.1
NetLD10_1: LD10.1 R35.1 | length 1.3
  Top Layer w0.35: LD10.1 R35.1
NetLD11_2: LD11.2 R22.1 | length 1.6
  Top Layer w0.25: LD11.2 R22.1
NetLD12_2: LD12.2 R23.1 | length 1.6
  Top Layer w0.25: LD12.2 R23.1
NetP2_1: P2.1 SW1.5
NetP4_L1: P4.L1 R13.2 | length 37.3
  Top Layer w0.25: P4.L1 3.732,31.164 5.08,32.512 5.08,43.688 9.398,48.006 R13.2
NetP4_L3: P4.L3 R14.2 | length 29.1
  Top Layer w0.25: P4.L3 3.732,44.626 8.509,49.403 R14.2
NetR1_1: R1.1 U1.9 | length 12.6
  Top Layer w0.25: R1.1 90.221,7.62 90.602,7.239 92.38,7.239 93.65,8.509 93.65,14.351 93.138,14.863 U1.9
NetR9_2: R9.2 U4.11 | length 2.6
  Top Layer w0.25: U4.11 86.96,35.011 87.427,34.544 R9.2
NetR10_2: R10.2 U4.10 | length 2.4
  Top Layer w0.25: R10.2 86.31,34.227 U4.10
NetR11_2: R11.2 U4.12 | length 2.8
  Top Layer w0.25: U4.12 87.61,35.504 88.697,34.417 R11.2
NetR12_2: R12.2 U4.9 | length 2.7
  Top Layer w0.25: R12.2 84.887,35.672 U4.9
RESET: C27.2 J3.3 M1.J1-2 SW3.1 | length 27.8
  Top Layer w0.25: M1.J1-2 76.093,22.637 76.378,22.352 79.172,22.352 J3.3 ; C27.2 73.571,7.993 SW3.1 v1(75.489,6.858)
  Bottom Layer w0.25: v1(75.489,6.858) 76.759,6.858 79.172,9.271 79.172,19.812 J3.3
STATUS: J3.23 LD8.2 M1.J1-12 | length 52.9
  Top Layer w0.25: v1(42.215,58.674) LD8.2 ; M1.J1-12 73.301,42.643 75.87,45.212 79.172,45.212 J3.23
  Bottom Layer w0.25: v1(42.215,58.674) 42.215,49.657 47.168,44.704 72.314,44.704 73.301,43.717 M1.J1-12
STATUS_LED0: J3.4 J6.2 M1.J3-2 | length 58.9
  Top Layer w0.25: M1.J3-2 71.301,22.603 72.263,21.641 75.565,21.641 76.124,21.082 J3.4
  Bottom Layer w0.25: J6.2 32.766,51.105 61.234,22.637 M1.J3-2
STATUS_LED1: J3.6 J7.2 M1.J3-3 | length 54.7
  Top Layer w0.25: M1.J3-3 72.316,23.622 J3.6
  Bottom Layer w0.25: J7.2 36.83,49.581 61.774,24.637 M1.J3-3
U_CTS0: J3.17 M1.J1-9 R12.1 | length 18.2
  Top Layer w0.25: M1.J1-9 75.245,36.637 76.2,37.592 79.172,37.592 J3.17 81.712,38.862 82.22,38.354 82.22,33.147 82.893,32.474 R12.1
U_DSR0: J3.19 M1.J1-10 SW4.1 | length 48.2
  Top Layer w0.25: v1(58.979,21.59) v1(58.979,33.655) ; M1.J1-10 74.578,38.637 76.073,40.132 79.172,40.132 J3.19
  Bottom Layer w0.25: v1(58.979,21.59) 58.979,18.542 63.297,14.224 SW4.1 ; v1(58.979,33.655) 62.967,37.643 72.307,37.643 M1.J1-10
U_DTR0: J3.11 LD6.2 M1.J1-6 | length 59.8
  Top Layer w0.25: v1(38.1,58.674) LD6.2
  Bottom Layer w0.25: v1(38.1,58.674) 40.056,56.718 40.056,49.149 57.582,31.623 72.315,31.623 M1.J1-6 75.205,30.637 75.87,29.972 79.172,29.972 J3.11
U_RTS0: J3.9 M1.J1-5 R9.1 | length 18.6
  Top Layer w0.25: v1(86.868,28.702) 87.427,29.261 R9.1
  Bottom Layer w0.25: M1.J1-5 75.3,28.637 76.505,27.432 79.172,27.432 J3.9 v1(86.868,28.702)
U_RXD0: J3.15 M1.J1-8 R11.1 | length 24.2
  Top Layer w0.25: R11.1 88.824,32.347 v1(88.824,30.48)
  Bottom Layer w0.25: M1.J1-8 73.716,35.052 79.172,35.052 J3.15 82.982,36.322 83.617,35.687 83.617,30.48 84.125,29.972 88.316,29.972 v1(88.824,30.48)
U_RXD2: J3.12 M1.J3-6 R6.2 | length 29
  Top Layer w0.25: M1.J3-6 72.296,29.642 74.905,29.642 76.505,31.242 J3.12 79.172,29.972 81.966,29.972 83.998,27.94 v1(83.998,23.749) ; R6.2 84.087,17.488 v1(86.919,20.32)
  Bottom Layer w0.25: v1(83.998,23.749) 86.919,20.828 v1(86.919,20.32)
U_TXD0: J3.7 M1.J1-4 R10.1 | length 19.7
  Top Layer w0.25: v1(85.014,26.162) 85.014,30.607 86.157,31.75 R10.1
  Bottom Layer w0.25: M1.J1-4 74.887,26.637 76.632,24.892 79.172,24.892 J3.7 v1(85.014,26.162)
U_TXD2: J3.10 M1.J3-5 R4.2 | length 27.5
  Top Layer w0.25: M1.J3-5 72.303,27.635 75.438,27.635 76.505,28.702 J3.10 79.172,27.432 81.966,27.432 82.474,26.924 v1(82.474,24.765) ; R4.2 83.236,15.24 82.728,15.748 82.728,18.034 v1(85.014,20.32)
  Bottom Layer w0.25: v1(82.474,24.765) 82.474,22.86 v1(85.014,20.32)
USB_5V: C3.2 L1.2 R3.2 SW1.2
USB_D_N: R5.2 U1.4 | length 12.6
  Top Layer w0.25: v1(89.205,11.309) 89.336,11.309 90.344,12.316 U1.4 ; v1(93.269,17.401) 93.294,17.401 93.677,17.018 R5.2
  Bottom Layer w0.25: v1(89.205,11.309) 89.205,11.311 89.332,11.438 91.579,11.438 92.38,12.239 92.38,16.512 v1(93.269,17.401)
USB_D_P: R7.2 U1.3 | length 11.8
  Top Layer w0.25: v1(89.205,12.067) 89.248,12.067 89.844,12.663 U1.3 ; v1(93.269,18.159) 93.294,18.159 93.677,18.542 R7.2
  Bottom Layer w0.25: v1(89.205,12.067) 89.205,12.065 89.332,11.938 91.372,11.938 91.88,12.446 91.88,16.902 93.137,18.159 v1(93.269,18.159)
USB_RXD: R4.1 U1.20 | length 6.8
  Top Layer w0.25: R4.1 85.268,15.24 84.887,15.621 84.887,17.145 85.268,17.526 86.284,17.526 86.792,17.018 86.792,16.637 87.566,15.863 U1.20
USB_TXD: R6.1 U1.21 | length 2.9
  Top Layer w0.25: R6.1 86.03,16.51 87.177,15.363 U1.21
VBUS: R2.2 R3.1 U1.8 | length 5.2
  Top Layer w0.25: U1.8 92.73,14.363 93.142,13.951 93.142,11.722 R3.1
  Top Layer w0.705: R2.2 R3.1
VCC_3.3V: C1.1 C2.2 C6.1 C7.2 C9.2 C18.1 C19.2 C20.2 C23.1 C24.1 J3.1 LD2.1 LD3.1 LD11.1 LD12.1 M1.J1-1 M1.J2-12 R1.2 R8.1 R13.1 R14.1 R15.2 R16.2 R19.1 R20.2 R21.2 R24.2 R26.2 R28.2 R33.2 R34.2 R35.2 SW2.2 SW3.2 SW5.2 U1.5 U1.6 U1.7 U3.2 U4.16 U5.5 | length 41.6
  Top Layer w0.25: U4.16 90.21,34.339 C9.2 ; U1.6 91.553,12.954 92.507,12.954 92.507,12.973 92.742,13.208 92.742,13.716 92.595,13.863 U1.7
  Top Layer w0.508: U5.5 23.622,31.242 24.168,31.788 C24.1 24.511,39.547 M1.J2-12
  Top Layer w0.705: J3.1 80.95,18.542 92.253,29.845 92.253,33.147 91.326,34.074 C9.2
pads on no net: M1.J2-1 M1.J2-9 P1.4 P3.1 P3.4 P3.6 P3.9 P4. P4.R4 P4.R5 P4.R6 SW1.3 SW1.6 SW4.2 U1.1 U1.10 U1.11 U1.12 U1.13 U1.14 U1.15 U1.17 U1.18 U1.19 U1.22 U1.23 U1.24 U3.4

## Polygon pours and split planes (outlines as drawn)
GND on Top Layer "TOP-GND" (solid, pour order 16): 105.004,8.382 105.004,21.717 94.92,21.717 93.396,23.241 93.396,29.845 94.412,30.861 100.762,30.861 101.27,31.369 101.27,45.571 100.613,46.228 94.92,46.228 93.015,48.133 93.015,66.294 91.999,67.31 18.923,67.31 12.7,61.087 12.7,21.59 11.656,20.546 5.306,20.546 3.683,18.923 3.683,11.176 12.065,2.794 93.65,2.794 99.238,8.382
CH_GND on Top Layer "TOP-CH-GND" (solid, pour order 18): 105.004,6.985 99.492,6.985 94.539,2.032 11.303,2.032 4.064,9.271 4.064,18.923 6.667,21.526 10.731,21.526 11.557,22.352 11.557,62.484 17.018,67.945 92.634,67.945 94.031,66.548 94.031,47.879 101.27,47.879 102.413,46.736 102.413,31.115 100.889,29.591 95.682,29.591 94.539,28.448 94.539,24.511 95.936,23.114 105.004,23.114 105.004,29.845 105.004,31.115 105.004,46.99 105.004,47.879 105.004,70 94.031,70 92.634,70 16.942,70 0,70 0,0 15.672,0 94.666,0 104.953,0
CH_GND on Bottom Layer "BOTTOM-CH-GND" (solid, pour order 10): 105.004,6.985 99.492,6.985 94.539,2.032 11.303,2.032 4.064,9.271 4.064,18.923 6.667,21.526 10.731,21.526 11.557,22.352 11.557,62.484 17.018,67.945 92.634,67.945 94.031,66.548 94.031,47.879 101.27,47.879 102.413,46.736 102.413,31.115 100.889,29.591 95.682,29.591 94.539,28.448 94.539,24.511 95.936,23.114 105.004,23.114 105.004,29.845 105.004,31.115 105.004,46.99 105.004,47.879 105.004,70 94.031,70 92.634,70 16.942,70 0,70 0,0 15.672,0 94.666,0 104.953,0
GND on Bottom Layer "BOTTOM-GND" (solid, pour order 14): 105.004,8.382 105.004,21.717 94.92,21.717 93.396,23.241 93.396,29.845 94.412,30.861 100.762,30.861 101.27,31.369 101.27,45.571 100.613,46.228 94.92,46.228 93.015,48.133 93.015,66.294 91.999,67.31 18.923,67.31 12.7,61.087 12.7,21.59 11.656,20.546 5.306,20.546 3.683,18.923 3.683,11.176 12.065,2.794 93.65,2.794 99.238,8.382

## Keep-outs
Keep-Out Layer:
  lines w0.254: 0,3.458 ccw(c3.458,3.458) 3.458,0 101.448,0 ccw(c101.448,3.555) 105.004,3.555 105.004,66.625 ccw(c101.629,66.625) 101.629,70 3.347,70 ccw(c3.347,66.653) 0,66.653 ; 0.004,3.458 0.004,66.653

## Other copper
Top Layer:
  region net USB_5V: 94.031,11.811 96.19,11.811 96.317,11.684 96.317,11.049 96.317,8.001 91.871,3.555 25.274,3.555 24.003,4.826 24.003,8.89 25.273,8.89 25.273,5.969 25.908,5.334 91.872,5.334 95.428,8.89 95.428,10.922 95.301,11.049 94.031,11.049
  region net VCC_3.3V: 41.199,17.272 42.215,17.272 42.215,15.113 42.977,14.351 50.851,14.351 51.359,14.859 51.359,18.161 51.359,19.685 51.359,53.924 50.673,54.61 45.263,54.61 43.739,56.134 43.739,62.611 43.104,63.246 21.082,63.246 18.161,60.325 18.161,51.562 18.415,51.308 23.545,51.308 24.689,50.165 24.689,46.482 28.245,43.053 28.245,42.418 27.872,42.045 27.348,42.045 26.975,42.418 23.673,45.72 23.673,49.657 23.038,50.292 17.526,50.292 16.637,51.181 16.637,61.214 19.812,64.389 45.568,64.389 46.482,65.303 48.108,66.929 82.296,66.929 82.652,66.573 82.652,65.38 82.652,64.77 81.712,64.77 81.712,65.732 81.305,66.167 73.66,66.167 73.254,65.761 73.254,64.77 72.314,64.77 72.314,65.735 71.882,66.167 64.008,66.167 63.627,65.786 63.627,64.77 62.611,64.77 62.611,65.786 62.23,66.167 54.483,66.167 53.95,65.634 53.95,64.77 53.061,64.77 53.061,65.684 52.578,66.167 51.105,66.167 48.768,66.167 48.311,65.71 48.311,63.373 46.533,63.373 45.39,62.23 45.39,60.452 45.39,57.353 46.609,56.134 52.959,56.134 53.899,55.194 53.95,51.714 53.959,51.069 54.609,50.419 68.961,50.419 68.961,49.276 54.61,49.276 53.862,48.528 53.862,47.893 53.862,45.503 53.862,19.722 54.788,18.796 72.187,18.796 72.568,19.177 72.568,21.082 72.72,21.234 73.812,21.234 73.965,21.082 73.965,19.939 73.965,19.177 74.346,18.796 75.997,17.145 79.045,17.145 79.68,17.78 79.68,19.05 79.934,19.304 80.95,19.304 81.204,19.05 81.204,15.621 82.347,14.478 82.347,8.636 82.982,8.001 86.538,8.001 87.173,8.636 87.173,10.287 87.3,10.414 88.951,10.414 89.205,10.668 90.348,10.668 90.729,11.049 90.729,13.538 91.491,13.538 91.491,11.049 91.872,10.668 91.872,10.414 91.872,9.652 89.332,9.652 88.951,9.271 88.951,8.382 88.951,7.62 88.951,6.985 88.011,6.045 81.001,6.045 80.823,6.223 80.823,13.462 78.537,15.748 74.6,15.748 73.584,16.764 69.647,16.764 69.266,16.383 69.266,6.858 68.631,6.223 65.583,6.223 65.202,6.604 65.202,7.112 65.583,7.493 67.996,7.493 68.378,7.875 68.377,16.383 67.996,16.764 54.153,16.764 53.645,16.256 53.645,12.954 53.137,12.446 42.342,12.446 41.199,13.589
  region net 5V: 21.463,14.478 22.733,14.478 22.733,11.938 23.368,11.303 28.321,11.303 28.702,11.684 28.702,15.748 30.099,17.145 30.861,17.145 40.005,17.145 40.005,15.113 31.242,15.113 30.48,14.351 30.48,10.414 29.591,9.525 23.368,9.525 22.733,8.89 22.733,6.35 21.463,6.35
  region net NetP2_1: 11.049,18.034 24.054,18.034 25.248,16.84 25.248,11.938 24.054,11.938 24.054,15.151 23.33,15.875 14.478,15.875 12.319,13.716 11.049,13.716
  pour cut-out: 105.004,8.636 98.984,8.636 93.805,3.458 12.417,3.458 4.826,11.049 4.826,19.431 5.588,20.193 13.843,20.193 14.605,20.955 14.605,22.86 15.494,23.749 17.907,23.749 18.415,24.257 18.415,40.64 17.907,41.148 13.716,41.148 13.081,41.783 13.081,45.593 13.589,46.101 13.589,61.29 17.958,65.659 19.228,66.929 91.745,66.929 92.634,66.04 92.634,48.895 92.634,47.879 94.539,45.974 99.873,45.974 100.635,45.212 100.635,32.385 99.873,31.623 94.412,31.623 93.269,30.48 93.269,23.114 94.92,21.463 105.004,21.463 105.004,23.368 96.19,23.368 95.174,24.384 95.174,28.448 96.063,29.337 101.143,29.337 102.794,30.988 102.794,46.609 101.27,48.133 95.809,48.133 94.539,49.403 94.539,66.929 92.927,68.326 16.561,68.326 11.049,62.814 11.049,22.987 10.287,22.225 4.191,22.225 2.413,20.447 2.413,9.906 10.414,1.905 94.92,1.905 100,6.985 105.004,6.985
  region net VCC_3.3V: 19.812,58.42 19.812,57.658 17.653,57.658 17.653,58.42
  region net VCC_3.3V: 19.812,55.626 19.812,54.864 17.653,54.864 17.653,55.626
  pour cut-out: 29.591,45.72 29.591,50.165 25.146,54.61 23.495,54.61 20.031,54.61 20.031,53.34 21.971,53.34
  pour cut-out: 30.607,49.149 30.607,52.324 25.654,57.277 24.384,57.277 19.05,57.277 19.05,56.007 23.749,56.007
  pour cut-out: 28.321,36.957 29.337,36.957 30.607,38.227 30.607,38.989 29.464,38.989 28.702,38.227 28.321,38.227
  pour cut-out: 88.138,5.334 88.138,7.747 92.888,7.747 92.888,5.385 92.837,5.334
  pour cut-out: 82.55,14.605 82.995,15.049 82.296,15.748 82.296,18.288 84.992,20.984 84.484,21.365 81.407,18.288 81.407,15.748 81.915,15.24
  pour cut-out: 104.14,8.382 104.14,21.59 104.648,21.59 104.775,21.463 104.775,8.382
  pour cut-out: 28.702,43.053 28.702,46.857 25.013,50.546 24.765,50.546 24.765,46.558 24.765,46.482
  pour cut-out: 89.535,37.846 89.535,37.338 93.091,37.338 93.091,37.846
  pour cut-out: 92.456,39.878 92.456,40.767 87.122,40.767 88.011,39.878
  pour cut-out: 45.593,60.071 46.482,60.071 46.482,62.23 48.514,62.23 48.514,63.119 45.593,63.119
  pour cut-out: 16.002,42.799 14.224,41.021 12.954,41.021 12.954,42.799
  pour cut-out: 84.201,22.606 83.947,23.241 84.582,23.876 85.09,23.622 85.09,23.368
  pour cut-out: 79.248,50.8 78.74,51.308 79.756,52.324 80.518,52.324 80.518,51.689
  pour cut-out: 74.041,42.164 74.803,42.164 77.216,44.577 77.216,44.831 75.946,44.831 74.041,42.926
  pour cut-out: 74.041,25.908 77.648,25.908 79.883,28.143 79.883,30.734 74.041,30.734
  pour cut-out: 71.247,33.147 71.247,34.163 69.345,34.16 67.315,36.19 67.315,34.882 69.05,33.147
  pour cut-out: 70.986,35.052 70.986,36.066 70.36,36.066 68.204,38.222 68.204,36.666 69.818,35.052
  pour cut-out: 74.041,34.163 75.311,34.163 77.089,35.941 77.089,37.084 76.708,37.084 75.946,36.322 74.041,36.322
  pour cut-out: 74.041,30.48 75.311,30.48 76.073,31.242 77.089,31.242 77.851,32.004 77.851,33.528 76.708,33.528 74.422,31.242 74.041,31.242
Bottom Layer:
  pour cut-out: 105.004,8.636 98.984,8.636 93.805,3.458 12.417,3.458 4.826,11.049 4.826,19.431 5.588,20.193 13.843,20.193 14.605,20.955 14.605,22.86 15.494,23.749 17.907,23.749 18.415,24.257 18.415,40.64 17.907,41.148 13.716,41.148 13.081,41.783 13.081,45.593 13.589,46.101 13.589,61.29 17.958,65.659 19.228,66.929 91.745,66.929 92.634,66.04 92.634,48.895 92.634,47.879 94.539,45.974 99.873,45.974 100.635,45.212 100.635,32.385 99.873,31.623 94.412,31.623 93.269,30.48 93.269,23.114 94.92,21.463 105.004,21.463 105.004,23.368 96.19,23.368 95.174,24.384 95.174,28.448 96.063,29.337 101.143,29.337 102.794,30.988 102.794,46.609 101.27,48.133 95.809,48.133 94.539,49.403 94.539,66.929 92.927,68.326 16.561,68.326 11.049,62.814 11.049,22.987 10.287,22.225 4.191,22.225 2.413,20.447 2.413,9.906 10.414,1.905 94.92,1.905 100,6.985 105.004,6.985
  pour cut-out: 77.216,25.273 77.216,29.591 76.581,30.226 73.406,30.226 73.406,28.448 73.406,26.797 75.057,26.797

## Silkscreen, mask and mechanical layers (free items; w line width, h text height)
Top Overlay:
  drawing of 1385 lines, arcs and shapes, not listed
  text "J1" at 89.377,68.295 h0.64
  text "J2" at 90.901,68.295 h0.64
  text "J4" at 92.552,68.295 h0.64
  text "J5" at 94.183,68.301 h0.64
  text "No" at 13.843,68.199 h0.64
  text "J6(STATUS_LED0)" at 16.51,68.199 h0.64
  text "GPIO Control" at 65.532,68.199 h1
  text "No" at 89.504,67.025 h0.64
  text "SHORT" at 93.187,67.025 h0.64
  text "SHORT" at 12.827,66.802 h0.64
  text "Using LED(LD9)" at 16.764,66.802 h0.64
  text "GPIO D" at 54.737,66.167 h0.64
  text "GPIO C" at 64.389,66.167 h0.64
  text "GPIO B" at 74.168,66.167 h0.64
  text "GPIO A" at 83.566,66.167 h0.64
  text "1-2" at 89.25,65.755 h0.64
  text "Digital I/O" at 91.536,65.755 h0.64
  text "depend" at 16.668,65.481 h0.64
  text "on" at 21.037,65.456 h0.64
  text "OPEN" at 12.954,65.399 h0.64
  text "STATUS" at 42.545,64.77 h0.64 r90
  text "PHY_LINK" at 38.481,64.643 h0.64 r90
  text "2-3" at 89.123,64.358 h0.64
  text "Analog In" at 91.536,64.358 h0.64
  text "No" at 13.843,63.754 h0.64
  text "J7(STATUS_LED1)" at 16.51,63.754 h0.64
  text "STATUS_LED0" at 31.369,62.611 h0.64 r90
  text "STATUS_LED1" at 35.56,62.611 h0.64 r90
  text "SHORT" at 12.827,62.357 h0.64
  text "Using LED(LD10)" at 16.764,62.357 h0.64
  text "GPIO" at 98.552,61.874 h0.64
  text "depend" at 16.668,61.036 h0.64
  text "on" at 21.037,61.011 h0.64
  text "OPEN" at 12.954,60.954 h0.64
  text "A" at 97.106,60.408 h0.64
  text "SW6" at 98.298,60.35 h0.64
  text "LD2" at 100.965,60.35 h0.64
  text "B" at 97.106,58.833 h0.64
  text "SW7" at 98.298,58.826 h0.64
  text "LD3" at 100.838,58.826 h0.64
  text "Analog" at 43.434,58.42 h0.8
  text "SW8" at 98.298,57.302 h0.64
  text "LD11" at 100.711,57.302 h0.64
  text "C" at 97.081,57.283 h0.64
  text "/100M_LINK" at 10.668,57.15 h0.8
  text "D" at 97.081,55.808 h0.64
  text "SW9" at 98.298,55.778 h0.64
  text "LD12" at 100.584,55.651 h0.64
  text "/10_100M_ACT" at 9.144,54.483 h0.8
  text "/COL" at 15.164,51.562 h0.8
  text "J8" at 26.848,44.12 h0.8
  text "J10" at 70.155,44.044 h0.8
  text "J9" at 72.873,44.018 h0.8
  text "ETHERNET" at 4.547,22.403 h0.8
  text "RS232" at 98.273,22.174 h0.8
  text "DATA" at 98.273,20.98 h0.8
  text "HW_TRIG" at 63.043,13.589 h0.8
  text "OFF" at 55.677,11.557 h0.8
  text "ON" at 68.758,11.557 h0.8
  text "ON" at 18.034,10.033 h0.8
  text "OFF" at 29.845,10.033 h0.8
  text "BOOT" at 77.648,10.033 h0.8
  text "5V POWER IN" at 4.928,8.661 h0.8
  text "APP_BOOT" at 63.043,8.509 h0.8
  text "USB" at 100.711,8.509 h0.8
  text "DEBUG" at 100.711,7.239 h0.8
  text "POWER_LED" at 47.295,6.731 h0.8
  text "OFF" at 55.677,6.477 h0.8
  text "ON" at 68.758,6.477 h0.8
  text "POWER SW" at 21.666,4.597 h0.8
  text "RESET" at 77.648,3.937 h0.8
  text "WIZ750SR-100-EVB V1.0" at 9.093,1.6 h1
Bottom Overlay:
  lines w0.2: 33.249,11.836 55.347,11.836 ; 39.853,1.168 55.347,1.168 ; 39.853,2.692 55.347,2.692 ; 39.853,4.47 55.347,4.47 ; 39.853,6.248 55.347,6.248 ; 39.853,9.042 55.347,9.042
  lines w0.254: 28.702,43.485 36.068,43.485 36.068,19.507 26.518,19.507 26.518,43.485 28.804,43.485 28.804,19.533 ; 28.829,23.622 36.068,23.622 ; 28.829,25.654 36.068,25.654 ; 28.829,27.559 36.068,27.559 ; 28.829,29.591 36.068,29.591 ; 28.829,31.623 36.068,31.623 ; 28.829,33.528 36.068,33.528 ; 28.829,35.56 36.068,35.56 ; 28.829,37.592 36.068,37.592 ; 28.829,39.624 36.068,39.624 ; 28.829,41.656 36.068,41.656 ; 28.956,21.768 36.068,21.768 ; 70.358,52.07 71.374,52.07 ; 70.358,57.15 71.374,57.15 ; 70.866,52.07 70.866,57.15 ; 71.755,49.53 72.771,49.53 ; 71.755,54.61 72.771,54.61 ; 72.263,49.53 72.263,54.61 ; 73.279,52.07 92.202,52.07 ; 73.279,54.61 92.202,54.61 ; 81.686,17.272 81.686,47.752 76.657,47.752 76.632,47.727 76.632,17.272 93.599,17.272 93.599,47.752 81.915,47.752 ; 81.686,19.812 93.599,19.812 ; 81.686,22.352 93.599,22.352 ; 81.686,24.892 93.599,24.892 ; 81.686,27.559 93.599,27.559 ; 81.686,29.972 93.599,29.972 ; 81.686,32.512 93.599,32.512 ; 81.686,35.052 93.599,35.052 ; 81.686,37.465 93.599,37.465 ; 81.686,40.132 93.599,40.132 ; 81.686,42.672 93.599,42.672 ; 81.712,45.212 93.523,45.212 ; 88.64,17.297 88.64,47.625 ; 73.279,49.53 73.279,57.15 92.202,57.15 92.202,49.53 73.279,49.53
  text "Digital I/O" at 69.977,54.229 h0.6
  text "Analog In" at 71.374,50.546 h0.6
  text "GND" at 86.106,46.228 h0.6
  text "STATUS" at 92.837,46.228 h0.6
  text "APP_BOOT" at 87.503,43.561 h0.6
  text "GND" at 91.821,43.561 h0.6
  text "GND" at 94.107,43.561 h0.64 r270
  text "VCC_3.3V" at 34.29,42.291 h0.6
  text "EX_GPIO_A" at 87.757,41.021 h0.6
  text "U_DSR0" at 92.964,41.021 h0.6
  text "COL" at 33.02,40.259 h0.6
  text "CTS" at 100.838,39.37 h0.64 r270
  text "EX_GPIO_B" at 87.757,38.481 h0.6
  text "U_CTS0" at 92.837,38.481 h0.6
  text "10_100M_ACT" at 35.56,38.354 h0.6
  text "TXD" at 94.107,38.1 h0.64 r270
  text "TX+" at 13.081,37.973 h0.8 r270
  text "TX-" at 15.621,36.83 h0.8 r270
  text "L4" at 1.778,36.576 h0.8 r270
  text "RTS" at 100.838,36.576 h0.64 r270
  text "NC" at 32.639,36.322 h0.6
  text "EX_GPIO_C" at 87.757,35.941 h0.6
  text "U_RXD0" at 92.837,35.941 h0.6
  text "RXD" at 94.107,35.306 h0.64 r270
  text "L3" at 1.778,34.798 h0.8 r270
  text "100M_LINK" at 35.052,34.29 h0.6
  text "EX_GPIO_D" at 87.757,33.401 h0.6
  text "GND" at 92.075,33.401 h0.6
  text "GND" at 33.274,32.258 h0.6
  text "U_RXD2" at 86.995,30.861 h0.6
  text "U_DTR0" at 92.837,30.861 h0.6
  text "MDI_T_P" at 34.29,30.353 h0.6
  text "U_TXD2" at 86.995,28.448 h0.6
  text "U_RTS0" at 92.837,28.448 h0.6
  text "MDI_T_N" at 34.29,28.321 h0.6
  text "L2" at 1.778,26.416 h0.8 r270
  text "GND" at 33.274,26.289 h0.6
  text "RX+" at 13.081,26.162 h0.8 r270
  text "BOOT" at 86.36,25.908 h0.6
  text "U_TXD0" at 92.837,25.908 h0.6
  text "L1" at 1.778,25.019 h0.8 r270
  text "RX-" at 15.621,24.892 h0.8 r270
  text "MDI_R_P" at 34.163,24.384 h0.6
  text "STATUS_LED1" at 88.265,23.241 h0.6
  text "GND" at 92.075,23.241 h0.6
  text "MDI_R_N" at 34.163,22.352 h0.6
  text "STATUS_LED0" at 88.392,20.701 h0.6
  text "RESET" at 92.583,20.701 h0.6
  text "NC" at 32.893,20.32 h0.6
  text "GND" at 86.106,18.161 h0.6
  text "VCC_3.3V" at 93.269,18.159 h0.6
  text "Board Model" at 55.347,10.566 h1.52
  text "WIZ750SR-100-EVB" at 55.347,9.296 h1.52
  text "Board Version" at 55.347,7.772 h1.52
  text "V1.0b" at 55.347,6.502 h1.52
  text "http://wizwiki.net" at 55.347,4.978 h1.52
  text "Designed by WIZnet" at 55.347,3.2 h1.52
  text "Made in KOREA" at 55.347,1.422 h1.52

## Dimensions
0.004,66.653 to 105.004,66.625 on Keep-Out Layer
101.629,70 to 101.448,0 on Keep-Out Layer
